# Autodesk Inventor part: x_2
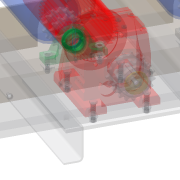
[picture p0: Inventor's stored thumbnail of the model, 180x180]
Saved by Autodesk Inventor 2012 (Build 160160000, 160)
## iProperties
Company: CAD-Verlag
Part Number: x_2
Document SubType Name: Modeling
Created: 2004-09
Material: Standard
Designer: Greiling
Manufacturer: Standard
Standards Organization: Custom
Density: 1 g/cm^3
Control State: 0
Master: False
Checked Out: False
Shininess: 64.0
Length Units: 11269
Angle Units: 11279
Time Units: 11290
Mass Units: 11283
Length Display Precision: 3
Angle Display Precision: 2
Compacted: True
Übersetzungsnorm: STEP AP214CD
Dateiname: w2c22665.stp
Vorprozessor: ACIS
Postprozessor: Build: 081d, Release: 8 SP1 - Date: Tue 01/26/2004
Gesendete Einheiten: MILLIMETERS
Unbestimmtheit: 1e-06
Density: 0.0
Volumn: 0.0
Area: 0.0
PropertySet Name: Model Information
Author: Jürgen Kronas
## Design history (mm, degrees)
feature "Basis1"
node "Volumenkörper1"
node "Volumenkörpern"
node "Oberflächenkörpern"
